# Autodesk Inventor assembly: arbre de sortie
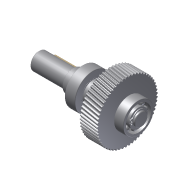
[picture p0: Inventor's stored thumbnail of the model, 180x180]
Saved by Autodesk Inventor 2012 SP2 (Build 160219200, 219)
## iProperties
Created: 2013-04
Part Number: arbre de sortie
Document SubType Name: Assembly
Designer: papa
Mass: 122.437 g
Surface Area: 411.578 cm^2
Volume: 122.437 cm^3
Density: 1 g/cm^3
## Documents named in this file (9)
- F:\Consmec\TBPMSMA\CCF\01-CCF Cermex Moteur\01-02 Dossier Rerssources CERMEX\02-01-04 - Dessins Cermex\02-01-04-01- Dessins 3D Cermex\02-01-04-01-01 - Dessins 3D Motoreducteur\02-01-04-01-01-01 - Composants 3D Motoreducteur R43\40 - Arbre de sortie.iam
- F:\Consmec\TBPMSMA\CCF\01-CCF Cermex Moteur\01-02 Dossier Rerssources CERMEX\02-01-04 - Dessins Cermex\02-01-04-01- Dessins 3D Cermex\02-01-04-01-01 - Dessins 3D Motoreducteur\02-01-04-01-01-01 - Composants 3D Motoreducteur R43\arbre de sortie.ipt
- F:\Consmec\TBPMSMA\CCF\01-CCF Cermex Moteur\01-02 Dossier Rerssources CERMEX\02-01-04 - Dessins Cermex\02-01-04-01- Dessins 3D Cermex\02-01-04-01-01 - Dessins 3D Motoreducteur\02-01-04-01-01-01 - Composants 3D Motoreducteur R43\clavette _6_6_32.ipt
- F:\Consmec\TBPMSMA\CCF\01-CCF Cermex Moteur\01-02 Dossier Rerssources CERMEX\02-01-04 - Dessins Cermex\02-01-04-01- Dessins 3D Cermex\02-01-04-01-01 - Dessins 3D Motoreducteur\02-01-04-01-01-01 - Composants 3D Motoreducteur R43\roulement 6004.ipt
- F:\Consmec\TBPMSMA\CCF\01-CCF Cermex Moteur\01-02 Dossier Rerssources CERMEX\02-01-04 - Dessins Cermex\02-01-04-01- Dessins 3D Cermex\02-01-04-01-01 - Dessins 3D Motoreducteur\02-01-04-01-01-01 - Composants 3D Motoreducteur R43\entretoise arbre de sortie.ipt
- F:\Consmec\TBPMSMA\CCF\01-CCF Cermex Moteur\01-02 Dossier Rerssources CERMEX\02-01-04 - Dessins Cermex\02-01-04-01- Dessins 3D Cermex\02-01-04-01-01 - Dessins 3D Motoreducteur\02-01-04-01-01-01 - Composants 3D Motoreducteur R43\clavette _6_6_16.ipt
- F:\Consmec\TBPMSMA\CCF\01-CCF Cermex Moteur\01-02 Dossier Rerssources CERMEX\02-01-04 - Dessins Cermex\02-01-04-01- Dessins 3D Cermex\02-01-04-01-01 - Dessins 3D Motoreducteur\02-01-04-01-01-01 - Composants 3D Motoreducteur R43\05 - Roue sortie - Z57.ipt
- F:\Consmec\TBPMSMA\CCF\01-CCF Cermex Moteur\01-02 Dossier Rerssources CERMEX\02-01-04 - Dessins Cermex\02-01-04-01- Dessins 3D Cermex\02-01-04-01-01 - Dessins 3D Motoreducteur\02-01-04-01-01-01 - Composants 3D Motoreducteur R43\roulement 6202.ipt
- F:\Consmec\TBPMSMA\CCF\01-CCF Cermex Moteur\01-02 Dossier Rerssources CERMEX\02-01-04 - Dessins Cermex\02-01-04-01- Dessins 3D Cermex\02-01-04-01-01 - Dessins 3D Motoreducteur\02-01-04-01-01-01 - Composants 3D Motoreducteur R43\anneau elastique 15 x 1.ipt
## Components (8 placed, 8 different names)
1. arbre de sortie:1 — Logement:1, Logement:2
2. clavette _6_6_32:1 — Logement:1, Logement:2
3. roulement 6004:1
4. entretoise arbre de sortie:1
5. clavette _6_6_16:1
6. roue sortie:1
7. roulement 6202:1
8. anneau elastique 15 x 1:1
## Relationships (2: Insert 2)
- Logement:1 [Insert]: arbre de sortie:1 ↔ clavette _6_6_32:1
- Logement:2 [Insert]: arbre de sortie:1 ↔ clavette _6_6_32:1
